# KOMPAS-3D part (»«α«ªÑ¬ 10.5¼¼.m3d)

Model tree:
1. Эскиз:1
2. Операция выдавливания:1
     Расстояние 1 = 8
3. Эскиз:2
4. Операция выдавливания:2
     Расстояние 1 = 1
5. Эскиз:3
6. Операция выдавливания:3
     Расстояние 1 = 2.5; Угол 1 = 8
7. Эскиз:4
8. Вырезать элемент выдавливания:1
     Расстояние 1 = 20
9. Эскиз:5
10. Вырезать элемент выдавливания:2
     Расстояние 1 = 3; Угол 1 = 19
11. Скругление:1
     Радиус = 1
12. Скругление:2
     Радиус = 1
13. Скругление:3
     Радиус = 1
14. Эскиз:6
15. Эскиз:7
16. Вырезать элемент выдавливания:3
     Расстояние 2 = 30; Расстояние 1 = 60
17. Эскиз:8
18. Вырезать элемент выдавливания:4
     Расстояние 2 = 30; Расстояние 1 = 60
19. Эскиз:9
20. Операция выдавливания:4
     Расстояние 1 = 10; Расстояние 2 = 62
21. Эскиз:10
22. Вырезать элемент выдавливания:5
     Расстояние 2 = 30; Расстояние 1 = 60
23. Скругление:4
     Радиус = 2
24. Скругление:5
     Радиус = 2
25. Эскиз:11
26. Вырезать элемент выдавливания:6
     Расстояние 1 = 10
27. Эскиз:12
28. Вырезать элемент выдавливания:7
     Расстояние 1 = 2.5; Угол 1 = 3
29. Эскиз:13
30. Вырезать элемент выдавливания:8
     Расстояние 2 = 40; Расстояние 1 = 30
31. Эскиз:14
32. Операция выдавливания:5
     Расстояние 1 = 10
33. Операция выдавливания:6
     Расстояние 1 = 2.5; Расстояние 2 = 5.94316
34. Эскиз:15
35. Вырезать элемент выдавливания:9
     Расстояние 1 = 20
36. Скругление:6
     Радиус = 1
37. Скругление:7
     Радиус = 1
38. Операция выдавливания:7
     Расстояние 1 = 2.5
